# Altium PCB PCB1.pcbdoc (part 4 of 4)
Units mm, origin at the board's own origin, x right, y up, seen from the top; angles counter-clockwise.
Board outline 77.9 x 109.02 mm, 4 copper layers (Top Layer, Inner1, Inner2, Bottom Layer); 129 components, 135 nets, 715 pads, 425 vias.
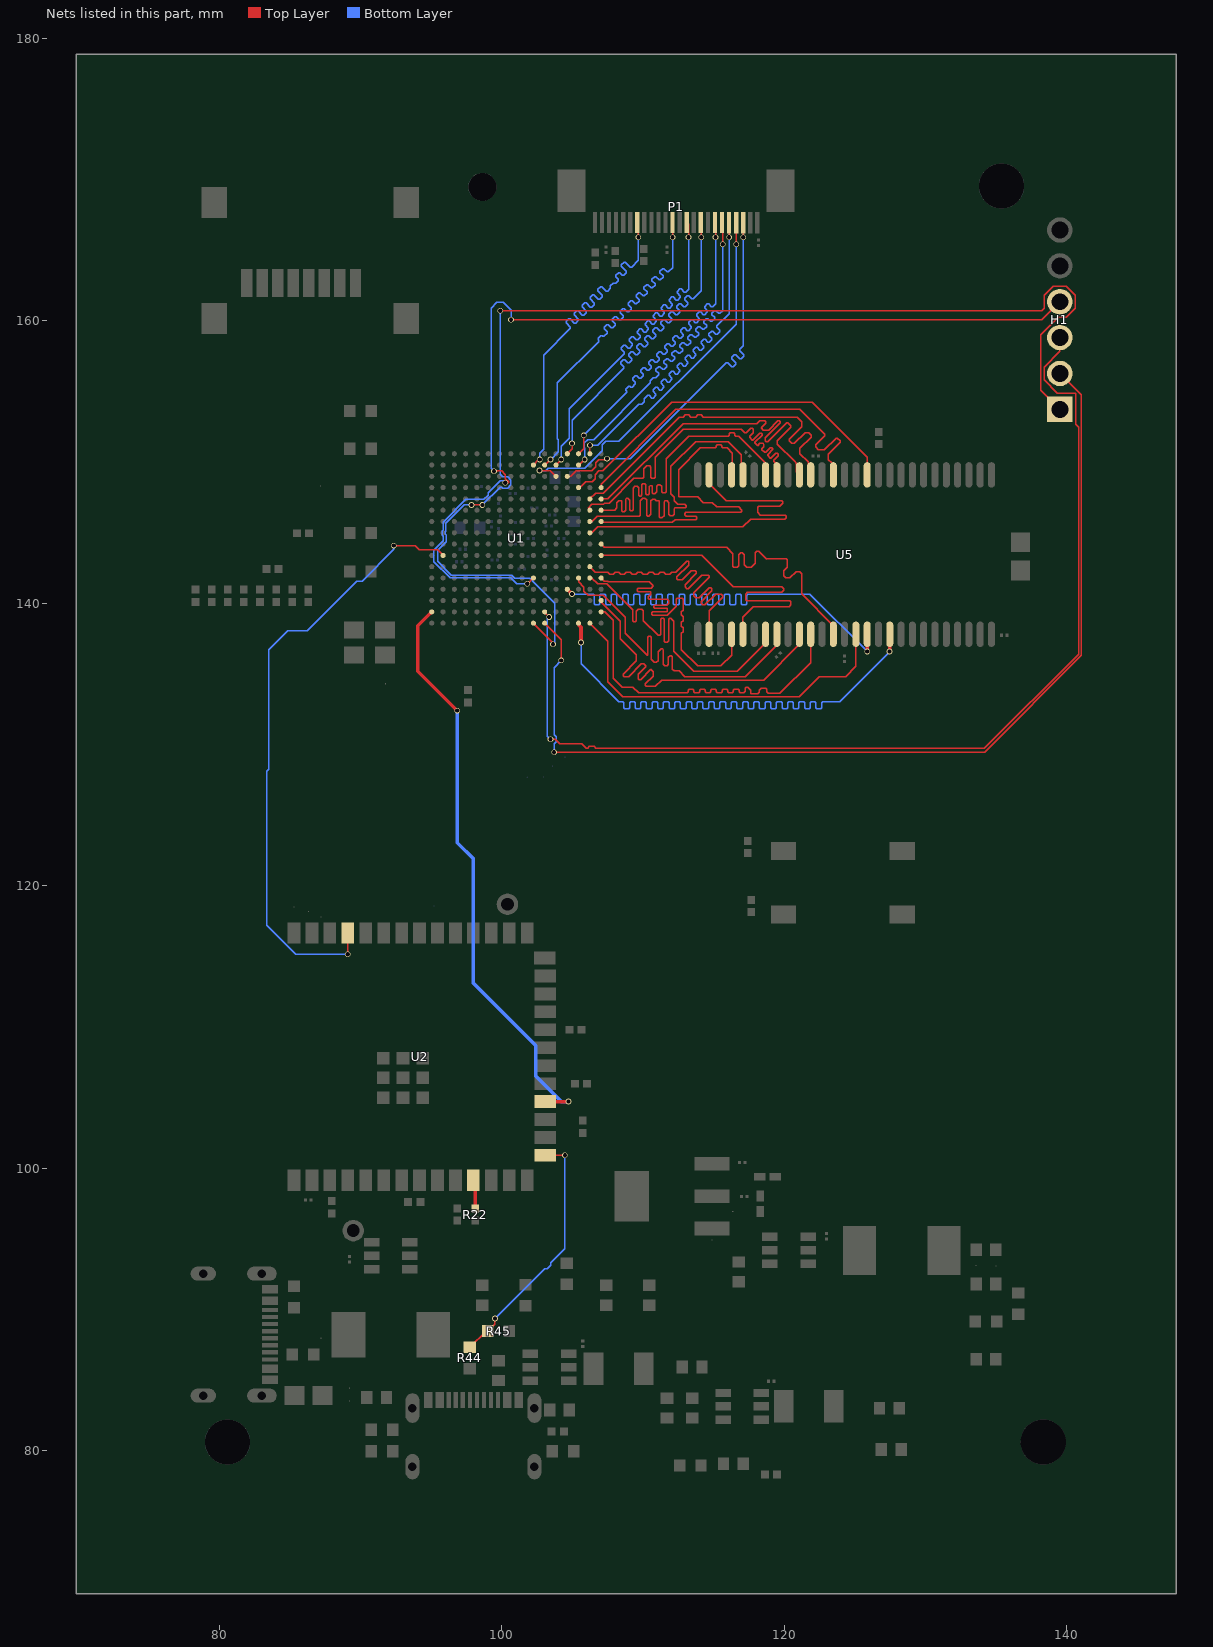
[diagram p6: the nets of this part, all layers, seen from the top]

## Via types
v1: diameter 0.4, hole 0.3, Top Layer to Bottom Layer, 387 vias
v2: diameter 0.5, hole 0.3, Top Layer to Bottom Layer, 36 vias
v3: diameter 1, hole 0.5, Top Layer to Bottom Layer, 2 vias

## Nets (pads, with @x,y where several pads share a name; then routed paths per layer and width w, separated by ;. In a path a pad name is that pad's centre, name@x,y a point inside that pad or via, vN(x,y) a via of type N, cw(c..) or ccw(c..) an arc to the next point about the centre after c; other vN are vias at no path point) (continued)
SD_DQ0: U1.L15 U5.2 | length 25
  Top Layer w0.1: U1.L15@106.224,142.585 106.606,142.203 107.473,142.203 107.543,142.132 107.543,142.116 107.614,142.045 107.873,142.045 107.943,142.116 107.943,142.132 108.014,142.203 108.273,142.203 108.343,142.132 108.343,142.116 108.414,142.045 108.673,142.045 108.743,142.116 108.743,142.132 108.814,142.203 109.073,142.203 109.143,142.132 109.143,142.116 109.214,142.045 109.473,142.045 109.543,142.116 109.543,142.132 109.614,142.203 109.873,142.203 109.943,142.132 109.943,142.116 110.014,142.045 110.273,142.045 110.343,142.116 110.343,142.132 110.414,142.203 110.673,142.203 110.743,142.132 110.743,142.116 110.814,142.045 111.073,142.045 111.143,142.116 111.143,142.132 111.214,142.203 111.473,142.203 111.543,142.132 111.543,142.116 111.614,142.045 111.873,142.045 111.943,142.116 111.943,142.132 112.014,142.203 112.314,142.203 113.074,142.963 113.187,142.963 113.216,142.934 113.216,142.68 112.393,141.857 112.393,141.725 112.454,141.664 112.755,141.664 113.39,142.299 113.699,142.299 113.77,142.228 113.77,142.128 112.962,141.32 112.962,141.156 113.089,141.029 113.179,141.029 114.139,141.989 114.594,141.989 114.665,141.918 114.665,141.824 113.597,140.755 113.597,140.521 113.724,140.394 113.978,140.394 114.684,141.1 114.796,141.1 114.867,141.029 114.867,140.876 114.105,140.114 114.105,140.013 114.232,139.886 114.359,139.886 115.121,140.648 115.519,140.648 115.639,140.527 115.639,140.427 114.665,139.453 U5.2@114.665,137.927
SD_DQ1: U1.M16 U5.4 | length 25
  Top Layer w0.1: U1.M16@107.024,141.785 107.24,141.569 107.5,141.569 107.539,141.531 110.428,141.531 110.729,141.229 110.558,141.058 109.66,141.058 109.589,140.987 109.589,140.887 109.66,140.817 110.507,140.817 110.549,140.775 110.549,140.636 110.351,140.439 110.351,140.339 110.422,140.268 111.691,140.268 111.798,140.161 111.798,139.992 111.671,139.865 110.803,139.865 110.738,139.8 110.738,139.708 110.803,139.643 111.691,139.643 111.691,139.409 111.674,139.392 110.676,139.392 110.605,139.321 110.605,139.221 110.676,139.151 111.691,139.151 112.327,139.787 112.327,140.267 112.398,140.338 112.764,140.338 112.835,140.267 112.835,139.505 112.708,139.378 112.708,139.174 112.828,139.054 112.828,138.774 112.708,138.654 112.708,138.374 112.828,138.254 112.828,137.974 112.708,137.854 112.708,136.711 113.851,135.568 115.502,135.568 116.265,136.331 U5.4@116.265,137.927
SD_DQ2: U1.K16 U5.5 | length 25.6
  Top Layer w0.1: U1.K16@107.024,143.385 114.162,143.385 116.391,141.156 119.82,141.156 119.947,141.029 119.947,140.902 119.803,140.758 117.372,140.758 117.262,140.648 117.262,140.243 117.322,140.184 120.384,140.184 120.455,140.113 120.455,139.886 120.329,139.76 117.789,139.76 117.048,139.019 117.048,138.198 117.065,138.181 U5.5@117.065,137.927
SD_DQ3: U1.M15 U5.7 | length 24.8
  Top Layer w0.1: U1.M15@106.224,141.785 106.303,141.785 106.318,141.77 106.366,141.77 106.769,141.367 107.417,141.367 109.263,139.52 109.263,138.743 109.334,138.672 109.434,138.672 109.505,138.743 109.505,139.42 109.66,139.574 109.914,139.574 110.014,139.474 110.014,138.77 111.057,137.727 111.184,137.727 111.242,137.785 111.242,138.87 111.312,138.941 111.412,138.941 111.483,138.87 111.483,137.301 111.565,137.219 111.692,137.219 111.815,137.342 111.815,138.87 111.874,138.929 111.958,138.929 112.18,138.706 112.18,136.604 113.597,135.187 116.65,135.187 118.521,137.058 118.521,137.656 118.538,137.673 118.538,137.8 U5.7@118.665,137.927
SD_DQ4: U1.M14 U5.8 | length 25.8
  Top Layer w0.1: U1.M14@105.424,141.785 105.424,141.525 105.806,141.143 105.806,140.862 106.102,140.567 107.182,140.567 108.744,139.005 108.744,137.854 110.302,136.296 110.334,136.328 110.334,137.6 110.404,137.671 110.504,137.671 110.575,137.6 110.575,136.023 110.776,135.822 110.93,135.822 111.049,135.941 111.049,136.563 111.267,136.782 111.367,136.782 111.438,136.711 111.438,135.668 111.538,135.568 111.692,135.568 111.784,135.66 111.784,136.155 111.902,136.274 112.002,136.274 112.073,136.203 112.073,135.336 112.2,135.209 112.54,135.209 112.943,134.806 117.214,134.806 119.622,137.213 119.622,137.77 U5.8@119.465,137.927
SD_DQ5: U1.P16 U5.10 | length 25.6
  Top Layer w0.1: U1.P16@107.024,140.185 107.024,140.076 108.369,138.73 108.369,137.493 109.503,136.36 109.503,135.906 108.573,134.977 108.573,134.877 108.644,134.806 108.964,134.806 109.853,135.695 110.041,135.695 110.168,135.568 110.168,135.502 109.647,134.981 109.647,134.666 109.718,134.595 109.818,134.595 110.543,135.32 110.711,135.151 110.711,134.829 110.161,134.278 110.161,134.178 110.231,134.107 110.866,134.107 111.311,134.552 118.542,134.552 121.065,137.075 U5.10@121.065,137.927
SD_DQ6: U1.R16 U5.11 | length 25.2
  Top Layer w0.1: U1.R16@107.024,139.385 107.288,139.385 107.882,138.791 107.882,134.679 108.513,134.047 109.275,134.047 109.676,133.647 113.117,133.647 113.188,133.717 113.188,133.846 113.259,133.917 113.517,133.917 113.588,133.846 113.588,133.717 113.659,133.647 113.917,133.647 113.988,133.717 113.988,133.846 114.059,133.917 114.317,133.917 114.388,133.846 114.388,133.717 114.459,133.647 114.717,133.647 114.788,133.717 114.788,133.846 114.859,133.917 115.117,133.917 115.188,133.846 115.188,133.717 115.259,133.647 115.517,133.647 115.588,133.717 115.588,133.846 115.659,133.917 115.917,133.917 115.988,133.846 115.988,133.717 116.059,133.647 116.317,133.647 116.388,133.717 116.388,133.846 116.459,133.917 116.717,133.917 116.788,133.846 116.788,133.717 116.859,133.647 117.136,133.647 117.236,133.747 117.236,133.973 117.307,134.044 117.407,134.044 117.613,133.838 117.613,133.587 118.125,133.587 118.225,133.687 118.225,133.846 118.352,133.973 118.677,133.973 118.748,133.902 118.748,133.716 118.848,133.616 119.679,133.616 121.852,135.789 U5.11@121.852,137.422
SD_DQ7: U1.J16 U5.13 | length 25.2
  Top Layer w0.1: U1.J16@107.024,144.185 107.259,143.95 115.91,143.95 116.347,143.513 116.347,142.611 116.418,142.54 116.659,142.54 116.759,142.64 116.759,143.442 116.896,143.578 117.016,143.578 117.155,143.44 117.155,142.705 117.319,142.54 117.648,142.54 117.931,142.823 117.931,143.585 118.042,143.696 118.185,143.696 118.753,143.128 118.757,143.132 120.13,143.132 120.201,143.061 120.201,142.562 119.947,142.308 119.947,141.934 120.09,141.791 120.387,141.791 120.822,142.226 121.09,142.226 121.219,142.097 121.219,140.662 ; 121.219,140.662 123.465,138.416 U5.13@123.465,137.927
SD_DQ8: U1.D16 U5.42 | length 25.2
  Top Layer w0.1: U1.D16@107.024,148.185 107.024,148.439 112.314,153.729 121.09,153.729 122.868,151.951 122.868,151.87 122.212,151.214 122.212,151.062 122.4,150.874 122.834,150.874 123.657,151.697 123.757,151.697 123.955,151.499 123.955,151.387 123.884,151.316 123.878,151.316 123.101,150.539 123.101,150.173 123.338,149.936 123.338,149.338 U5.42@123.465,149.211
SD_DQ9: U1.E15 U5.44 | length 25
  Top Layer w0.1: U1.E15@106.224,147.385 106.642,147.803 107.182,147.803 112.537,153.157 112.837,153.157 112.907,153.228 112.907,153.277 112.978,153.348 113.237,153.348 113.307,153.277 113.307,153.228 113.378,153.157 113.723,153.157 113.794,153.228 113.794,153.277 113.865,153.348 114.123,153.348 114.194,153.277 114.194,153.228 114.265,153.157 120.899,153.157 121.217,152.84 121.217,152.501 120.328,151.612 120.328,151.503 120.515,151.316 120.709,151.316 121.471,152.078 121.725,152.078 121.894,151.908 121.894,151.767 121.09,150.963 121.09,150.584 121.674,150 121.674,149.401 U5.44@121.865,149.211
SD_DQ10: U1.E16 U5.45 | length 25
  Top Layer w0.1: U1.E16@107.024,147.385 107.507,147.385 112.835,152.713 118.052,152.713 118.25,152.911 118.606,152.911 118.677,152.84 118.677,152.754 118.344,152.421 118.502,152.263 118.874,152.263 119.522,152.911 119.622,152.911 119.693,152.84 119.693,152.773 118.647,151.727 118.647,151.5 118.717,151.429 118.817,151.429 120.151,152.763 120.251,152.763 120.455,152.559 120.455,152.459 119.494,151.498 119.494,151.271 120.717,150.048 120.717,150.043 120.851,149.909 120.851,149.311 120.951,149.211 U5.45@121.065,149.211
SD_DQ11: U1.F15 U5.47 | length 25.1
  Top Layer w0.1: U1.F15@106.224,146.585 106.097,146.712 106.097,146.737 106.363,147.003 107.182,147.003 107.273,147.094 107.597,147.094 109.335,148.832 109.97,148.832 110.041,148.903 110.041,149.538 110.244,149.741 110.449,149.741 110.549,149.641 110.549,148.903 110.62,148.832 110.769,148.832 110.84,148.903 110.84,150.337 112.835,152.332 116.942,152.332 117.202,152.072 117.286,152.072 117.617,152.403 117.717,152.403 117.788,152.332 117.788,152.078 117.534,151.824 117.534,151.74 117.719,151.554 117.772,151.554 118.24,152.022 118.352,152.022 118.423,151.951 118.423,151.906 117.915,151.398 117.915,151.359 118.114,151.16 118.271,151.316 118.487,151.316 118.55,151.253 118.55,151.093 118.392,150.935 118.392,150.882 118.593,150.681 118.677,150.681 119.002,151.006 119.114,151.006 119.185,150.935 119.185,150.886 118.804,150.505 118.804,150.47 118.999,150.275 119.046,150.275 119.395,150.625 119.495,150.625 119.566,150.554 119.566,150.456 119.228,150.118 119.228,150.046 119.465,149.809 U5.47@119.465,149.211
SD_DQ12: U1.F16 U5.48 | length 25.1
  Top Layer w0.1: U1.F16@107.024,146.585 107.977,146.585 108.136,146.744 108.136,147.125 108.263,147.252 108.429,147.252 108.473,147.208 108.473,146.561 108.544,146.49 108.644,146.49 108.752,146.598 108.752,147.36 108.81,147.418 108.898,147.418 109.033,147.283 109.033,146.621 109.108,146.546 109.208,146.546 109.279,146.617 109.279,148.141 109.406,148.268 109.592,148.268 109.672,148.188 109.672,147.633 109.743,147.562 109.811,147.562 109.914,147.664 109.914,148.39 109.976,148.453 110.11,148.453 110.18,148.382 110.18,147.76 110.251,147.689 110.351,147.689 110.422,147.76 110.422,148.268 110.486,148.332 110.612,148.332 110.647,148.297 110.647,147.816 110.718,147.745 110.818,147.745 110.959,147.887 110.959,148.297 111.057,148.395 111.184,148.395 111.311,148.268 111.311,147.887 111.382,147.816 111.55,147.816 111.621,147.887 111.621,150.229 113.216,151.824 116.024,151.824 116.095,151.895 116.095,152.007 116.166,152.078 116.424,152.078 116.495,152.007 116.495,151.895 116.566,151.824 116.772,151.824 118.606,149.989 118.606,149.311 118.665,149.252 U5.48@118.665,149.211
SD_DQ13: U1.G15 U5.50 | length 25.1
  Top Layer w0.1: U1.G15@106.224,145.785 106.365,145.785 106.747,146.167 109.718,146.167 109.787,146.236 109.787,147.252 109.97,147.435 110.112,147.435 110.239,147.308 110.239,146.236 110.309,146.165 110.409,146.165 110.549,146.305 110.549,147.252 110.676,147.379 110.803,147.379 110.93,147.252 111.146,147.252 111.146,146.109 111.217,146.038 111.317,146.038 111.476,146.197 111.476,147.195 111.533,147.252 111.692,147.252 111.819,147.125 111.819,146.309 111.919,146.209 112.1,146.209 112.2,146.309 112.2,146.702 112.241,146.744 112.962,146.744 113.033,146.815 113.033,146.915 112.954,146.993 112.459,146.993 112.2,147.252 112.2,147.493 111.957,147.736 111.957,149.682 113.718,151.443 116.01,151.443 116.946,150.506 116.946,149.329 U5.50@117.065,149.211
SD_DQ14: U1.G16 U5.51 | length 25
  Top Layer w0.1: U1.G16@107.024,145.785 107.087,145.721 112.066,145.721 112.26,145.915 113.724,145.915 113.795,145.986 113.795,146.086 113.724,146.156 113.041,146.156 112.929,146.269 112.929,146.33 113.023,146.424 116.899,146.424 116.97,146.495 116.97,146.595 116.75,146.815 115.204,146.815 114.894,147.125 114.27,147.125 113.851,147.544 112.501,147.544 112.501,149.458 114.041,150.998 115.105,150.998 115.176,151.069 115.176,151.143 115.246,151.214 115.505,151.214 115.576,151.143 115.576,151.069 115.646,150.998 115.946,150.998 116.311,150.633 116.311,149.546 U5.51@116.328,149.528
SD_DQ15: U1.H15 U5.53 | length 25.3
  Top Layer w0.1: U1.H15@106.224,144.985 106.351,144.985 106.769,145.403 117.055,145.403 117.612,145.96 120.039,145.96 120.145,146.065 120.145,146.165 120.074,146.236 118.296,146.236 118.098,146.434 118.098,146.8 118.169,146.871 119.68,146.871 119.891,147.081 119.891,147.181 119.82,147.252 115.883,147.252 114.792,148.343 U5.53@114.792,149.084
SD_DQM0: U1.T15 U5.15 | length 25.8
  Top Layer w0.1: U1.T15@106.224,138.585 107.501,137.307 107.501,134.425 108.539,133.387 121.034,133.387 122.453,134.806 124.352,134.806 125.065,135.519 U5.15@125.065,137.8
SD_DQM1: U1.D14 U5.39 | length 25.9
  Top Layer w0.1: U1.D14@105.424,148.185 105.513,148.185 105.931,148.603 106.382,148.603 106.606,148.827 106.606,149.107 106.866,149.367 107.146,149.367 112.016,154.237 121.963,154.237 125.874,150.327 125.874,149.338 U5.39@125.747,149.211
SD_RAS_N: U1.T14 U5.18 | length 43.8
  Top Layer w0.254: U1.T14@105.469,138.419 105.596,138.292 v1(105.596,137.219) ; v1(127.44,136.584) 127.465,136.609 U5.18@127.465,137.8
  Bottom Layer w0.1: v1(105.596,137.219) 105.596,135.695 108.263,133.028 108.563,133.028 108.634,132.957 108.634,132.591 108.704,132.52 108.963,132.52 109.034,132.591 109.034,132.957 109.104,133.028 109.363,133.028 109.434,132.957 109.434,132.591 109.504,132.52 109.763,132.52 109.834,132.591 109.834,132.957 109.904,133.028 110.163,133.028 110.234,132.957 110.234,132.591 110.304,132.52 110.563,132.52 110.634,132.591 110.634,132.957 110.704,133.028 110.963,133.028 111.034,132.957 111.034,132.591 111.104,132.52 111.363,132.52 111.434,132.591 111.434,132.957 111.504,133.028 111.763,133.028 111.834,132.957 111.834,132.591 111.904,132.52 112.163,132.52 112.234,132.591 112.234,132.957 112.304,133.028 112.563,133.028 112.634,132.957 112.634,132.591 112.704,132.52 112.963,132.52 113.034,132.591 113.034,132.957 113.104,133.028 113.363,133.028 113.434,132.957 113.434,132.591 113.504,132.52 113.763,132.52 113.834,132.591 113.834,132.957 113.904,133.028 114.163,133.028 114.234,132.957 114.234,132.591 114.304,132.52 114.563,132.52 114.634,132.591 114.634,132.957 114.704,133.028 114.963,133.028 115.034,132.957 115.034,132.591 115.104,132.52 115.363,132.52 115.434,132.591 115.434,132.957 115.504,133.028 115.763,133.028 115.834,132.957 115.834,132.591 115.904,132.52 116.163,132.52 116.234,132.591 116.234,132.957 116.304,133.028 116.563,133.028 116.634,132.957 116.634,132.591 116.704,132.52 116.963,132.52 117.034,132.591 117.034,132.957 117.104,133.028 117.363,133.028 117.434,132.957 117.434,132.591 117.504,132.52 117.763,132.52 117.834,132.591 117.834,132.957 117.904,133.028 118.163,133.028 118.234,132.957 118.234,132.591 118.304,132.52 118.563,132.52 118.634,132.591 118.634,132.957 118.704,133.028 118.963,133.028 119.034,132.957 119.034,132.591 119.104,132.52 119.363,132.52 119.434,132.591 119.434,132.957 119.504,133.028 119.763,133.028 119.834,132.957 119.834,132.591 119.904,132.52 120.163,132.52 120.234,132.591 120.234,132.957 120.304,133.028 120.563,133.028 120.634,132.957 120.634,132.591 120.704,132.52 120.963,132.52 121.034,132.591 121.034,132.957 121.104,133.028 121.363,133.028 121.434,132.957 121.434,132.591 121.504,132.52 121.763,132.52 121.834,132.591 121.834,132.957 121.904,133.028 122.163,133.028 122.234,132.957 122.234,132.591 122.304,132.52 122.563,132.52 122.634,132.591 122.634,132.957 122.704,133.028 123.931,133.028 127.44,136.536 v1(127.44,136.584)
SD_WE_N: U1.N13 U5.16 | length 43.3
  Top Layer w0.254: U1.N13@104.624,140.985 v1(104.961,140.648) ; v1(125.865,136.584) U5.16@125.865,137.8
  Bottom Layer w0.1: v1(104.961,140.648) 106.469,140.648 106.54,140.577 106.54,139.957 106.61,139.886 106.869,139.886 106.94,139.957 106.94,140.577 107.01,140.648 107.269,140.648 107.34,140.577 107.34,139.957 107.41,139.886 107.669,139.886 107.74,139.957 107.74,140.577 107.81,140.648 108.069,140.648 108.14,140.577 108.14,139.957 108.21,139.886 108.469,139.886 108.54,139.957 108.54,140.577 108.61,140.648 108.869,140.648 108.94,140.577 108.94,139.957 109.01,139.886 109.269,139.886 109.34,139.957 109.34,140.577 109.41,140.648 109.669,140.648 109.74,140.577 109.74,139.957 109.81,139.886 110.069,139.886 110.14,139.957 110.14,140.577 110.21,140.648 110.469,140.648 110.54,140.577 110.54,139.957 110.61,139.886 110.869,139.886 110.94,139.957 110.94,140.577 111.01,140.648 111.269,140.648 111.34,140.577 111.34,139.957 111.41,139.886 111.669,139.886 111.74,139.957 111.74,140.577 111.81,140.648 112.069,140.648 112.14,140.577 112.14,139.957 112.21,139.886 112.469,139.886 112.54,139.957 112.54,140.577 112.61,140.648 112.869,140.648 112.94,140.577 112.94,139.957 113.01,139.886 113.269,139.886 113.34,139.957 113.34,140.577 113.41,140.648 113.669,140.648 113.74,140.577 113.74,139.957 113.81,139.886 114.069,139.886 114.14,139.957 114.14,140.577 114.21,140.648 114.469,140.648 114.54,140.577 114.54,139.957 114.61,139.886 114.869,139.886 114.94,139.957 114.94,140.577 115.01,140.648 115.269,140.648 115.34,140.577 115.34,139.957 115.41,139.886 115.669,139.886 115.74,139.957 115.74,140.577 115.81,140.648 116.069,140.648 116.14,140.577 116.14,139.957 116.21,139.886 116.469,139.886 116.54,139.957 116.54,140.577 116.61,140.648 116.869,140.648 116.94,140.577 116.94,139.957 117.01,139.886 117.269,139.886 117.34,139.957 117.34,140.577 117.41,140.648 121.801,140.648 v1(125.865,136.584)
SDA: R22.1 U2.11 | length 1.9
  Top Layer w0.254: R22.1@98.098,97.214 U2.11@98.098,99.132
SSPI_CS_N: U1.R1 U2.18 | length 41.3
  Top Layer w0.254: U1.R1@95.024,139.385 94.039,138.4 94.039,135.187 v1(96.833,132.393) ; U2.18@103.188,104.707 v1(104.707,104.707)
  Bottom Layer w0.254: v1(96.833,132.393) 96.833,123.039 97.976,121.896 97.976,113.089 102.394,108.671 102.394,106.512 104.199,104.707 v1(104.707,104.707)
TCK: H1.1 U1.T10 | length 88.4
  Top Layer w0.1: v1(97.845,146.957) 98.056,146.957 98.065,146.967 98.382,146.967 98.392,146.957 98.57,146.957 v1@98.611,146.998 ; v1(99.881,160.714) 138.219,160.714 138.403,160.898 138.403,161.805 139.048,162.451 139.961,162.451 140.607,161.805 140.607,160.892 139.961,160.247 139.384,160.247 138.152,159.014 138.152,155.082 H1.1@139.505,153.729 ; U1.T10@102.224,138.585 103.608,137.201 v1(103.608,137.092)
  Bottom Layer w0.1: v1(97.845,146.957) 97.329,146.957 96.026,145.654 96.026,145.097 95.976,145.048 95.976,144.896 96.038,144.834 96.038,144.335 95.436,143.733 95.436,142.963 96.408,141.991 100.706,141.991 100.92,141.777 101.952,141.777 103.739,139.991 103.739,137.223 v1(103.608,137.092) ; v1(98.611,146.957) 99.881,148.227 99.965,148.227 100.057,148.135 100.39,148.135 100.626,148.371 100.626,148.704 100.39,148.939 100.057,148.939 99.881,149.116 v1(99.881,160.714)
TDI: H1.3 U1.R11 | length 74.5
  Top Layer w0.1: U1.R11@103.024,139.385 103.024,139.337 v1(103.337,139.024) ; v1(103.437,130.361) 103.765,130.361 104.092,130.034 105.642,130.034 105.95,129.726 106.064,129.726 106.191,129.853 106.524,129.853 106.651,129.726 134.171,129.726 140.829,136.384 140.829,152.449 140.616,152.662 140.616,154.875 139.34,154.875 138.403,155.812 138.403,156.725 139.505,157.827 H1.3@139.505,158.809
  Bottom Layer w0.1: v1(103.337,139.024) 103.206,138.893 103.206,130.592 v1(103.437,130.361)
TDO: H1.4 U1.M10 | length 72.1
  Top Layer w0.1: v1(99.436,149.349) 99.648,149.349 99.666,149.367 99.982,149.367 100.242,149.107 100.242,148.827 100.466,148.603 100.466,148.567 100.436,148.537 v1(100.224,148.537) ; v1(100.643,160.079) 138.235,160.079 H1.4@139.505,161.349 ; v1(101.786,141.375) 101.814,141.375 U1.M10@102.224,141.785
  Bottom Layer w0.1: v1(99.436,149.349) 99.225,149.561 99.225,160.897 99.625,161.297 100.106,161.297 100.643,160.76 v1(100.643,160.079) ; v1(100.224,148.537) 100.097,148.664 99.867,148.664 99.013,147.81 99.013,147.653 98.719,147.359 97.448,147.359 95.826,145.737 95.826,145.18 95.776,145.131 95.776,144.813 95.838,144.751 95.838,144.418 95.182,143.762 95.182,142.934 96.325,141.791 100.624,141.791 101.039,141.375 v1(101.786,141.375)
TMS: H1.2 U1.T11 | length 70.7
  Top Layer w0.1: U1.T11@103.024,138.585 104.199,137.41 v1(104.199,135.949) ; v1(103.691,129.451) 134.179,129.451 141.029,136.301 141.029,154.745 H1.2@139.505,156.269
  Bottom Layer w0.1: v1(103.691,129.451) 103.691,130.046 103.839,130.194 103.839,130.527 103.691,130.675 103.691,135.441 v1(104.199,135.949)
TX: U1.K2 U2.37 | length 43.6
  Top Layer w0.1: v1@89.081,115.121 U2.37@89.081,116.632 ; v1@92.261,144.077 93.851,144.077 94.126,143.802 95.405,143.802 ; 95.406,143.803 U1.K2@95.824,143.385
  Bottom Layer w0.1: v1(89.081,115.142) 85.382,115.142 83.348,117.176 83.348,128.105 83.498,128.255 83.498,136.711 84.822,138.035 86.194,138.035 89.729,141.57 90.097,141.57 92.336,143.808 v1(92.336,144.077)
USB_VBUS: R44.1 R45.2 U2.15 | length 18
  Top Layer w0.1: R44.1@97.722,87.299 98.873,88.451 R45.2@99,88.451 99.5,88.95 v1(99.5,89.34) ; U2.15@103.061,100.897 v1(104.453,100.897)
  Bottom Layer w0.1: v1(99.5,89.34) 103.026,92.866 103.222,92.866 103.458,93.102 103.458,93.298 104.453,94.293 v1(104.453,100.897)
VSYNC: P1.7 U1.B10 | length 27.1
  Top Layer w0.1: U1.B10@102.224,149.785 102.619,150.18 v1(102.667,150.18) ; P1.7@109.581,166.951 109.66,166.872 v1(109.66,165.921)
  Bottom Layer w0.1: v1(102.667,150.18) 102.667,150.613 102.95,150.895 102.95,157.56 104.845,159.455 104.845,159.555 104.536,159.864 104.536,159.964 104.719,160.147 104.819,160.147 105.128,159.838 105.228,159.838 105.411,160.021 105.411,160.121 105.101,160.43 105.101,160.53 105.284,160.713 105.384,160.713 105.693,160.403 105.793,160.403 105.976,160.586 105.976,160.686 105.667,160.995 105.667,161.095 105.85,161.278 105.95,161.278 106.259,160.969 106.359,160.969 106.542,161.152 106.542,161.252 106.233,161.561 106.233,161.661 106.416,161.844 106.516,161.844 106.825,161.535 106.925,161.535 107.108,161.718 107.108,161.818 106.798,162.127 106.798,162.227 106.981,162.41 107.081,162.41 107.39,162.1 107.49,162.1 107.677,162.287 107.677,162.48 107.864,162.666 108.056,162.666 108.239,162.849 108.239,162.949 108.073,163.115 108.073,163.215 108.256,163.398 108.356,163.398 108.522,163.232 108.622,163.232 108.805,163.415 108.805,163.515 108.46,163.859 108.46,163.959 108.643,164.142 108.743,164.142 109.088,163.798 109.188,163.798 109.66,164.27 v1(109.66,165.921)
Y2: P1.19 U1.B14 | length 27
  Top Layer w0.1: U1.B14@105.424,149.785 105.812,150.173 v1(105.85,150.173) ; P1.19@115.58,166.951 115.629,166.903 v1(115.629,165.413)
  Bottom Layer w0.1: v1(105.85,150.173) 105.85,151.001 105.829,151.022 105.829,151.355 106.064,151.591 106.506,151.591 110.51,155.595 110.51,155.761 110.71,155.961 110.876,155.961 111.091,156.176 111.091,156.276 110.903,156.464 110.903,156.564 111.086,156.747 111.186,156.747 111.374,156.559 111.474,156.559 111.657,156.742 111.657,156.842 111.469,157.03 111.469,157.13 111.652,157.313 111.752,157.313 111.94,157.125 112.04,157.125 112.223,157.308 112.223,157.408 112.035,157.596 112.035,157.696 112.218,157.879 112.318,157.879 112.506,157.691 112.606,157.691 112.788,157.873 112.788,157.973 112.6,158.161 112.6,158.261 112.783,158.444 112.883,158.444 113.071,158.256 113.171,158.256 113.354,158.439 113.354,158.539 113.166,158.727 113.166,158.827 113.349,159.01 113.449,159.01 113.637,158.822 113.737,158.822 113.92,159.005 113.92,159.105 113.732,159.293 113.732,159.393 113.915,159.576 114.015,159.576 114.203,159.388 114.303,159.388 114.486,159.571 114.486,159.671 114.298,159.859 114.298,159.959 114.48,160.141 114.58,160.141 114.768,159.953 114.868,159.953 115.051,160.136 115.051,160.236 114.863,160.424 114.863,160.524 115.046,160.707 115.146,160.707 115.334,160.519 115.434,160.519 115.629,160.714 v1(115.629,165.413)
Y3: P1.21 U1.C12 | length 27
  Top Layer w0.1: v1(102.661,149.396) 103.413,149.396 U1.C12@103.824,148.985 ; v1(116.583,165.413) P1.21@116.583,166.948
  Bottom Layer w0.1: v1(102.661,149.396) 103.11,149.396 103.269,149.555 105.867,149.555 107.099,150.787 107.099,151.228 107.334,151.464 108.284,151.464 116.583,159.763 v1(116.583,165.413)
Y4: P1.22 U1.C13 | length 27
  Top Layer w0.1: U1.C13@104.624,148.985 104.884,148.985 105.266,149.367 106.346,149.367 106.642,149.663 106.642,149.943 106.866,150.167 107.358,150.167 v1(107.432,150.241) ; v1(117.083,165.921) P1.22@117.083,166.948
  Bottom Layer w0.1: v1(107.432,150.241) 109.093,150.241 115.888,157.036 115.988,157.036 116.269,156.755 116.369,156.755 116.552,156.938 116.552,157.038 116.271,157.319 116.271,157.419 116.454,157.602 116.554,157.602 116.835,157.321 116.935,157.321 117.117,157.503 117.117,157.603 116.836,157.884 116.836,157.984 117.083,158.231 v1(117.083,165.921)
Y5: P1.20 U1.A15 | length 27
  Top Layer w0.1: U1.A15@106.224,150.585 106.231,150.592 v1(106.231,151.189) ; v1(116.083,165.921) P1.20@116.083,166.948
  Bottom Layer w0.1: v1(106.231,151.189) 106.776,151.189 109.674,154.086 109.774,154.086 109.782,154.078 109.882,154.078 110.065,154.261 110.065,154.361 110.057,154.369 110.057,154.469 110.317,154.729 110.417,154.729 110.616,154.531 110.716,154.531 110.899,154.714 110.899,154.814 110.7,155.012 110.7,155.112 110.883,155.295 110.983,155.295 111.181,155.096 111.281,155.096 111.464,155.279 111.464,155.379 111.266,155.578 111.266,155.678 111.448,155.861 111.548,155.861 111.747,155.662 111.847,155.662 112.03,155.845 112.03,155.945 111.831,156.144 111.831,156.244 112.014,156.427 112.114,156.427 112.313,156.228 112.413,156.228 112.596,156.411 112.596,156.511 112.397,156.709 112.397,156.809 112.58,156.992 112.68,156.992 112.879,156.794 112.979,156.794 113.161,156.976 113.161,157.076 112.963,157.275 112.963,157.375 113.146,157.558 113.246,157.558 113.444,157.359 113.544,157.359 113.727,157.542 113.727,157.642 113.528,157.841 113.528,157.941 113.711,158.124 113.811,158.124 114.01,157.925 114.11,157.925 114.293,158.108 114.293,158.208 114.094,158.406 114.094,158.506 114.277,158.689 114.377,158.689 114.576,158.491 114.676,158.491 114.858,158.673 114.858,158.773 114.66,158.972 114.66,159.072 114.843,159.255 114.943,159.255 115.141,159.056 115.241,159.056 115.424,159.239 115.424,159.339 115.225,159.538 115.225,159.638 116.083,160.495 v1(116.083,165.921)
Y6: P1.18 U1.A14 | length 27.1
  Top Layer w0.1: U1.A14@105.424,150.585 105.789,150.95 v1(105.789,151.884) ; P1.18@115.081,166.951 115.121,166.911 v1(115.121,165.921)
  Bottom Layer w0.1: v1(105.789,151.884) 108.828,154.923 108.828,155.023 108.782,155.068 108.782,155.168 108.965,155.351 109.065,155.351 109.11,155.305 109.21,155.305 109.439,155.534 109.439,155.634 109.254,155.82 109.254,155.92 109.437,156.103 109.537,156.103 109.722,155.917 109.822,155.917 110.005,156.1 110.005,156.2 109.82,156.385 109.82,156.485 110.003,156.668 110.103,156.668 110.288,156.483 110.388,156.483 110.571,156.666 110.571,156.766 110.385,156.951 110.385,157.051 110.568,157.234 110.668,157.234 110.854,157.049 110.954,157.049 111.136,157.231 111.136,157.331 110.951,157.517 110.951,157.617 111.134,157.8 111.234,157.8 111.419,157.614 111.519,157.614 111.702,157.797 111.702,157.897 111.517,158.082 111.517,158.182 111.7,158.365 111.8,158.365 111.985,158.18 112.085,158.18 112.268,158.363 112.268,158.463 112.082,158.648 112.082,158.748 112.265,158.931 112.365,158.931 112.551,158.746 112.651,158.746 112.833,158.928 112.833,159.028 112.648,159.214 112.648,159.314 112.831,159.497 112.931,159.497 113.116,159.311 113.216,159.311 113.399,159.494 113.399,159.594 113.214,159.78 113.214,159.88 113.397,160.062 113.497,160.062 113.682,159.877 113.782,159.877 113.965,160.06 113.965,160.16 113.779,160.345 113.779,160.445 113.962,160.628 114.062,160.628 114.248,160.443 114.348,160.443 114.531,160.626 114.531,160.726 114.345,160.911 114.345,161.011 114.528,161.194 114.628,161.194 114.813,161.008 114.913,161.008 115.121,161.216 v1(115.121,165.921)
Y7: P1.16 U1.A13 | length 26.9
  Top Layer w0.1: U1.A13@104.624,150.585 104.961,150.922 v1(104.961,151.316) ; P1.16@114.081,166.95 114.105,166.926 v1(114.105,165.921)
  Bottom Layer w0.1: v1(104.961,151.316) 104.961,152.967 108.639,156.645 108.639,156.745 108.421,156.962 108.421,157.062 108.604,157.245 108.704,157.245 108.922,157.028 109.022,157.028 109.205,157.211 109.205,157.311 108.987,157.528 108.987,157.628 109.17,157.811 109.27,157.811 109.487,157.593 109.587,157.593 109.77,157.776 109.77,157.876 109.553,158.094 109.553,158.194 109.736,158.377 109.836,158.377 110.053,158.159 110.153,158.159 110.336,158.342 110.336,158.442 110.118,158.659 110.118,158.759 110.301,158.942 110.401,158.942 110.619,158.725 110.719,158.725 110.902,158.908 110.902,159.008 110.684,159.225 110.684,159.325 110.867,159.508 110.967,159.508 111.184,159.29 111.284,159.29 111.467,159.473 111.467,159.573 111.25,159.791 111.25,159.891 111.433,160.074 111.533,160.074 111.75,159.856 111.85,159.856 112.033,160.039 112.033,160.139 111.815,160.356 111.815,160.456 111.998,160.639 112.098,160.639 112.316,160.422 112.416,160.422 112.599,160.605 112.599,160.705 112.381,160.922 112.381,161.022 112.564,161.205 112.664,161.205 112.881,160.987 112.981,160.987 113.164,161.17 113.164,161.27 112.947,161.488 112.947,161.588 113.13,161.771 113.23,161.771 113.447,161.553 113.547,161.553 114.105,162.111 v1(114.105,165.921)
Y8: P1.14 U1.B12 | length 27
  Top Layer w0.1: U1.B12@103.824,149.785 104.199,150.16 v1(104.199,150.173) ; P1.14@113.081,166.951 113.212,166.82 v1(113.212,165.917)
  Bottom Layer w0.1: v1(104.199,150.173) 104.199,151.122 104.761,151.684 104.761,153.783 108.659,157.681 108.659,157.781 108.441,157.998 108.441,158.098 108.624,158.281 108.724,158.281 108.942,158.064 109.042,158.064 109.235,158.257 109.235,158.357 109.018,158.575 109.018,158.675 109.2,158.857 109.3,158.857 109.518,158.64 109.618,158.64 109.801,158.823 109.801,158.923 109.583,159.14 109.583,159.24 109.766,159.423 109.866,159.423 110.084,159.206 110.184,159.206 110.366,159.388 110.366,159.488 110.149,159.706 110.149,159.806 110.332,159.989 110.432,159.989 110.649,159.771 110.749,159.771 110.932,159.954 110.932,160.054 110.715,160.272 110.715,160.372 110.897,160.554 110.997,160.554 111.215,160.337 111.315,160.337 111.498,160.52 111.498,160.62 111.28,160.837 111.28,160.937 111.463,161.12 111.563,161.12 111.781,160.903 111.881,160.903 112.063,161.085 112.063,161.185 111.846,161.403 111.846,161.503 112.029,161.686 112.129,161.686 112.346,161.468 112.446,161.468 112.629,161.651 112.629,161.751 112.412,161.969 112.412,162.069 112.595,162.252 112.695,162.252 112.912,162.034 113.012,162.034 113.212,162.234 v1(113.212,165.917)
Y9: P1.12 U1.B11 | length 27
  Top Layer w0.1: U1.B11@103.024,149.785 103.412,150.173 v1(103.437,150.173) ; v1(112.081,165.921) P1.12@112.081,166.951
  Bottom Layer w0.1: v1(103.437,150.173) 103.999,150.735 103.999,151.582 103.924,151.657 103.924,155.613 106.836,158.525 106.836,158.625 106.809,158.652 106.809,158.752 106.992,158.935 107.092,158.935 107.119,158.908 107.219,158.908 107.445,159.134 107.445,159.234 107.228,159.452 107.228,159.552 107.41,159.734 107.51,159.734 107.728,159.517 107.828,159.517 108.011,159.7 108.011,159.8 107.793,160.017 107.793,160.117 107.976,160.3 108.076,160.3 108.294,160.083 108.394,160.083 108.576,160.265 108.576,160.365 108.359,160.583 108.359,160.683 108.542,160.866 108.642,160.866 108.859,160.648 108.959,160.648 109.142,160.831 109.142,160.931 108.925,161.149 108.925,161.249 109.108,161.432 109.208,161.432 109.425,161.214 109.525,161.214 109.708,161.397 109.708,161.497 109.49,161.714 109.49,161.814 109.673,161.997 109.773,161.997 109.991,161.78 110.091,161.78 110.274,161.963 110.274,162.063 110.056,162.28 110.056,162.38 110.239,162.563 110.339,162.563 110.556,162.345 110.656,162.345 110.839,162.528 110.839,162.628 110.622,162.846 110.622,162.946 110.805,163.129 110.905,163.129 111.122,162.911 111.222,162.911 111.405,163.094 111.405,163.194 111.187,163.411 111.187,163.511 111.37,163.694 111.47,163.694 111.688,163.477 111.788,163.477 112.081,163.77 v1(112.081,165.921)
pads on no net: P1.1 P1.10 SCREW1.1 SCREW2.1 SCREW3.1 SCREW4.1 U1.A9 U1.B3 U1.B8 U1.B13 U1.B15 U1.B16 U1.C1 U1.C2 U1.C3 U1.C4 U1.C5 U1.C6 U1.C9 U1.C10 U1.C11 U1.C14 U1.C15 U1.C16 U1.D1 U1.D3 U1.D4 U1.D5 U1.D6 U1.D7 U1.D8 U1.D9 U1.D10 U1.D11 U1.D12 U1.D13 U1.E3 U1.E4 U1.E5 U1.E6 U1.E7 U1.E8 U1.E9 U1.E10 U1.E11 U1.E12 U1.E13 U1.E14 U1.F3 U1.F4 U1.F5 U1.F12 U1.F13 U1.F14 U1.G3 U1.G4 U1.G5 U1.G12 U1.G13 U1.G14 U1.H2 U1.H3 U1.H4 U1.H5 U1.H12 U1.H13 U1.H14 U1.J3 U1.J4 U1.J5 U1.J12 U1.J13 U1.K3 U1.K4 U1.K5 U1.K13 U1.K14 U1.K15 U1.L1 U1.L2 U1.L3 U1.L4 U1.L5 U1.L13 U1.L14 U1.L16 U1.M2 U1.M3 U1.M4 U1.M5 U1.M6 U1.M7 U1.M9 U1.M11 U1.M12 U1.M13 U1.N1 U1.N3 U1.N4 U1.N5 U1.N6 U1.N7 U1.N8 U1.N9 U1.N11 U1.N12 U1.N14 U1.N16 U1.P1 U1.P2 U1.P3 U1.P4 U1.P5 U1.P6 U1.P7 U1.P8 U1.P11 U1.P12 U1.P13 U1.P14 U1.P15 U1.R2 U1.R3 U1.R4 U1.R5 U1.R6 U1.R7 U1.R8 U1.R12 U1.R14 U1.T13 U2.4 U2.16 U2.26 U2.28 U2.29 U2.30 U2.32 U2.33 U2.34 U2.35 U2.38 U2.39 U5.40 U8.4 USB1.A6 USB1.A7 USB1.A8 USB1.B6 USB1.B7 USB1.B8 USB2.A8 USB2.B6 USB2.B7 USB2.B8
copper on no net: | length 20.4
  Top Layer w0.1: 86.292,118.169 86.541,117.92 86.541,116.632 ; 87.181,117.788 87.811,117.158 87.811,116.632 ; 89.081,99.132 89.31,98.903 v1(89.31,97.498) ; 97.971,116.632 97.971,117.267 99.508,118.804 100.135,118.804 100.389,118.55 ; v1@102.675,139.886 102.725,139.886 103.024,140.185
  Top Layer w0.254: v1(94.166,140.217) 94.992,140.217 95.024,140.185 ; v1(94.337,142.724) 94.477,142.585 95.024,142.585 ; v1(94.42,141.029) 94.98,141.029 95.024,140.985 ; v1(95.421,140.629) 95.824,140.226 95.824,140.185 ; v1(96.219,140.542) 96.219,140.58 96.624,140.985 ; v1(96.976,139.785) 97.024,139.785 97.424,140.185 ; v1(97.087,140.648) 97.424,140.985 ; v1@97.826,139.736 97.826,139.787 98.224,140.185 ; v1(97.849,140.648) 97.887,140.648 98.224,140.985 ; v1@98.611,140.648 98.687,140.648 99.024,140.985 ; v1(98.692,139.805) 99.024,140.137 99.024,140.185 ; v1@99.373,140.521 99.373,140.534 99.824,140.985
  Bottom Layer w0.1: v1(89.31,97.498) 89.467,97.341 89.467,95.563 ; v1(93.15,142.597) 94.21,142.597 v1(94.337,142.724) ; v1(102.676,139.885) 103.056,139.505 103.056,139.378
  other v1: 97.824,139.737 99.406,140.554 98.625,140.634

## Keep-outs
Board Outline Layer:
  lines w0.254: 77.402,77.525 141.402,77.525 141.402,172.525 77.402,172.525 77.402,77.525

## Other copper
Top Layer:
  region net GND: 85.019,118.692 85.527,118.692 85.527,118.29 85.014,118.29 85.019,118.296
  region net GND: 86.929,88.143 87.437,88.143 87.437,87.742 86.924,87.742 86.929,87.747
  region net GND: 88.961,83.698 89.469,83.698 89.469,83.297 88.956,83.297 88.961,83.302
  region net +5V: 88.942,84.606 89.45,84.606 89.45,84.205 88.937,84.205 88.942,84.21
  region net +1V8: 116.09,97.123 116.598,97.123 116.598,96.722 116.085,96.722 116.09,96.727
  region net GND: 114.609,95.093 115.117,95.093 115.117,94.692 114.604,94.692 114.609,94.697
  region net GND: 134.726,93.253 135.234,93.253 135.234,92.852 134.72,92.852 134.726,92.857
  region net +3V3: 86.899,148.49 87.407,148.49 87.407,148.088 86.894,148.088 86.899,148.094
  region net GND: 91.501,134.498 92.009,134.498 92.009,134.097 91.496,134.097 91.501,134.102
  region net +1V1: 133.326,93.292 133.834,93.292 133.834,92.891 133.32,92.891 133.326,92.896
  region: 86.04,118.369 86.548,118.369 86.548,117.968 86.035,117.968 86.04,117.973
  region: 86.929,117.988 87.437,117.988 87.437,117.587 86.924,117.587 86.929,117.592
Bottom Layer:
  region net DONE: 103.312,128.656 103.82,128.656 103.82,128.255 103.307,128.255 103.312,128.26
  region net +1V1: 104.201,129.291 104.709,129.291 104.709,128.89 104.196,128.89 104.201,128.895
  region net PROGRAMN: 101.534,127.873 102.042,127.873 102.042,127.472 101.529,127.472 101.534,127.477
  region net INITN: 94.93,118.75 95.438,118.75 95.438,118.349 94.925,118.349 94.93,118.354
  region net GND: 102.677,127.894 103.185,127.894 103.185,127.493 102.672,127.493 102.677,127.498
  region: 102.738,139.553 103.178,139.807 103.378,139.459 102.934,139.203 102.936,139.21

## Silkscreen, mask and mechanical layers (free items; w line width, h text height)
Top Silkscreen Layer:
  text "JTAG" at 137.621,157.622 h3.05 r90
